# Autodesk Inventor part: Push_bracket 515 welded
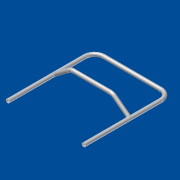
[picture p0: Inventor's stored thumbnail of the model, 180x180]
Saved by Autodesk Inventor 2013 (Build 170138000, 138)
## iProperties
Shininess: 69.0
Length Units: 11269
Angle Units: 11279
Time Units: 11290
Mass Units: 11283
Length Display Precision: 3
Angle Display Precision: 2
Created: 2001-05
Part Number: Push_bracket 515 welded
Material: Standard
Document SubType Name: Modellieren
Designer: dl
Density: 1 g/cm^3
Density: 0.0
Volumn: 0.0
Area: 0.0
PropertySet Name: Model Information
Control State: 0
Master: False
Checked Out: False
Author: dl
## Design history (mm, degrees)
body "Solid1"
derived "Push_bracket_assembly 515 wide ipart.iam"
  feature "Cross_girder_Push_bracket ipart [d1=515 mm].ipt:1" dims "d10" = 10
  feature "Push_bracket ipart [d1=515].ipt:1" dims "d10" = 10
fillet "Fillet1" dims "d8" = 3
workaxis "Work Axis1"
workaxis "Work Axis2"
workplane "Work Plane1"
workaxis "Work Axis3"
workplane "Work Plane2"
other parameters: "d2" = 90 deg, "d5" = 0, "d9" = 0
